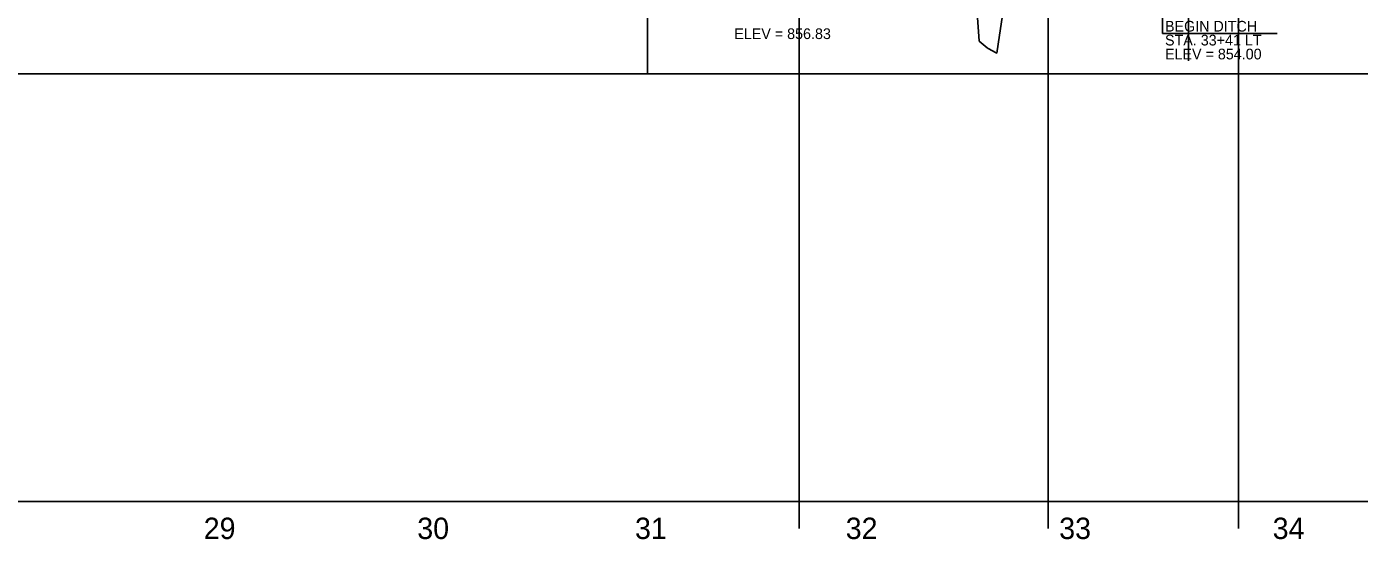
# Model space of a CAD drawing. Extents: x 1968019 to 1983409, y 545058 to 567558.
# Drawn here: x 1970653 to 1971276, y 566291 to 566531 of the extents above; entities that cross this region are included whole.
import ezdxf

# ---------------------------------------------------------------- set-up
doc = ezdxf.new("R2010")
doc.units = 0
for name, color, linetype in [('Exist Profile Cell', 7, 'Continuous'), ('Exist Vertical Profile Ground Line', 7, 'Continuous'), ('Exist Vertical Profile Horizontal Axis Label Major', 7, 'Continuous'), ('Prop Vertical Profile Ditch Grade Left Label', 7, 'Continuous'), ('Scratch_Level_1', 7, 'Continuous'), ('Scratch_Level_8', 7, 'Continuous')]:
    doc.layers.add(name, color=color, linetype=linetype)

msp = doc.modelspace()

# ---------------------------------------------------------------- linework, layer by layer
at = {"layer": 'Exist Profile Cell'}
msp.add_line((1968842.96, 566308.43), (1972642.96, 566308.43), dxfattribs=at)
at = {"layer": 'Exist Vertical Profile Ground Line'}
msp.add_lwpolyline([(1971097.26, 566537.05), (1971098.21, 566523.79), (1971101.85, 566520.68), (1971102.38, 566520.38), (1971106.13, 566518.4), (1971106.38, 566518.22), (1971106.99, 566522.3), (1971109.93, 566542.19)], dxfattribs=at)
at = {"layer": 'Prop Vertical Profile Ditch Grade Left Label'}
for p in [(1971183.96, 566578.43), (1971237.47, 566527.34)]:
    msp.add_line(p, (1971183.96, 566527.34), dxfattribs=at)
at = {"layer": 'Scratch_Level_1'}
for p, q in [((1971219.46, 566295.93), (1971219.46, 566786.18)), ((1971013.96, 566295.93), (1971013.96, 566768.12)), ((1971130.46, 566295.93), (1971130.46, 566707.38)), ((1971196.05, 566593.46), (1971196.05, 566514.57))]:
    msp.add_line(p, q, dxfattribs=at)
at = {"layer": 'Scratch_Level_8'}
for points in [[(1969542.96, 566508.43), (1970942.96, 566508.43), (1970942.96, 566812.08), (1970792.94, 566812.08), (1970792.94, 567008.42), (1969542.96, 567008.43)], [(1970942.96, 566508.43), (1972342.96, 566508.43), (1972342.96, 567008.43), (1970942.96, 567008.43)]]:
    msp.add_lwpolyline(points, close=True, dxfattribs=at)

# ---------------------------------------------------------------- texts
at = {"layer": 'Exist Vertical Profile Horizontal Axis Label Major'}
for s, p in [('29', (1970735.47, 566290.93)), ('30', (1970835.34, 566290.93)), ('31', (1970937.18, 566290.93)), ('32', (1971035.73, 566290.93)), ('33', (1971135.57, 566290.93)), ('34', (1971235.41, 566290.93))]:
    msp.add_text(s, height=10, dxfattribs=at).set_placement(p)
at = {"layer": 'Prop Vertical Profile Ditch Grade Left Label'}
for s, p in [('BEGIN DITCH', (1971185.06, 566528.26)), ('ELEV = 856.83', (1970983.61, 566524.76)), ('STA. 33+41 LT', (1971185.06, 566521.76)), ('ELEV = 854.00', (1971185.06, 566515.26))]:
    msp.add_text(s, height=5, dxfattribs=at).set_placement(p)

doc.saveas('drawing.dxf')
